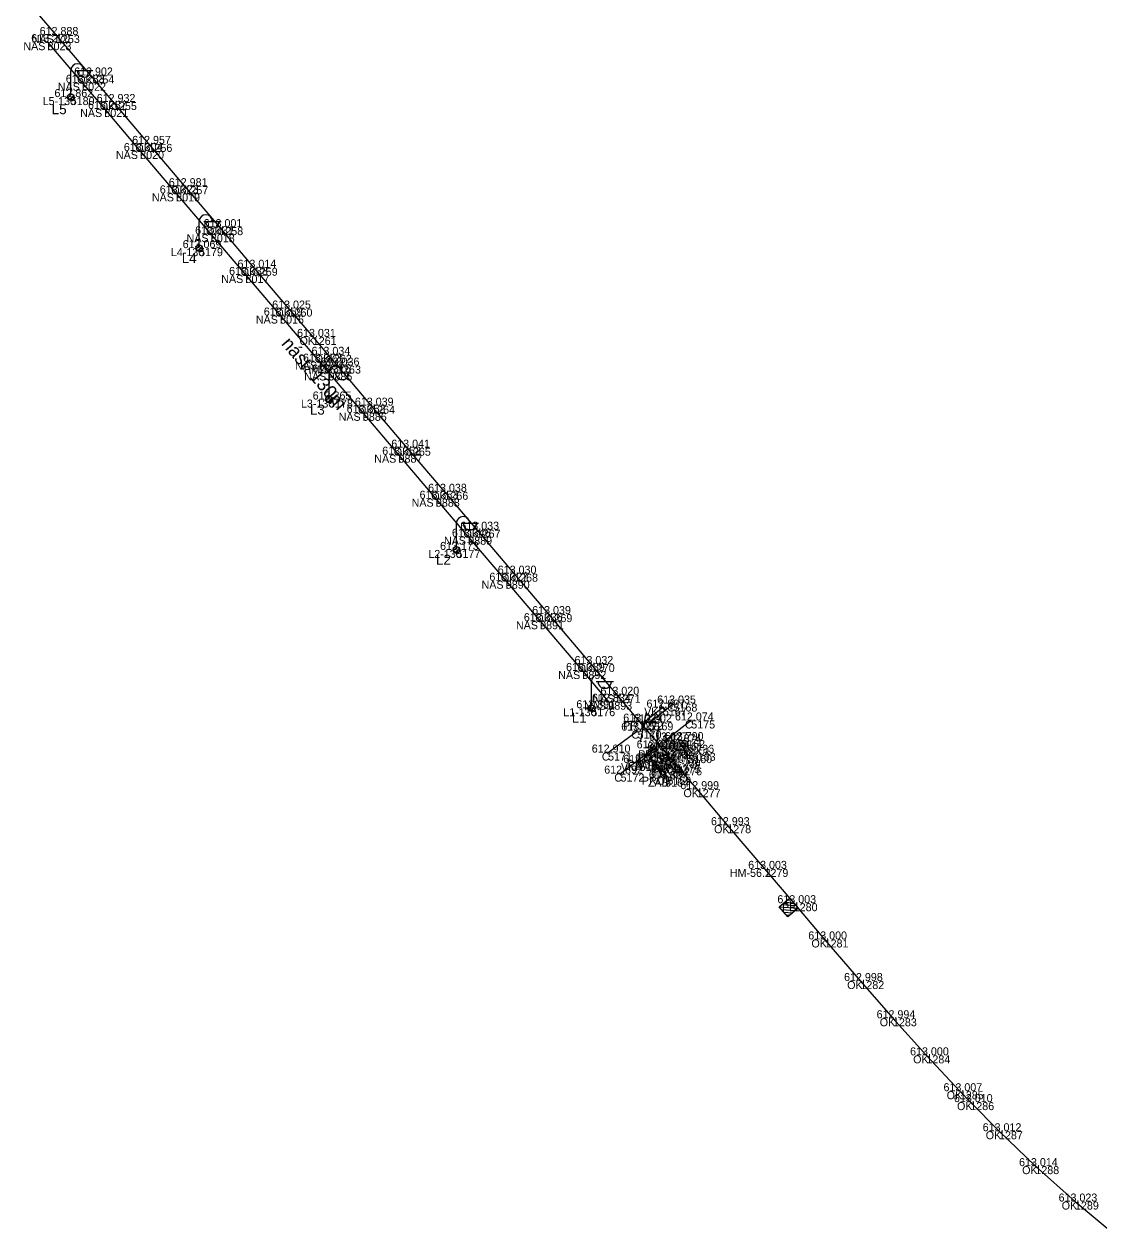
# Model space of a CAD drawing. Extents: x -631472 to -620808, y -1122356 to -1115125.
# Drawn here: x -625291.5 to -625130.5, y -1118428.6 to -1118247.1 of the extents above; entities that cross this region are included whole.
import ezdxf

# ---------------------------------------------------------------- set-up
doc = ezdxf.new("R2010")
doc.units = 0
for name, color, linetype in [('Vrstva 1', 7, 'Continuous'), ('Vrstva 14', 7, 'Continuous'), ('Vrstva 17', 7, 'Continuous'), ('Vrstva 18', 7, 'Continuous'), ('Vrstva 25', 7, 'Continuous'), ('Vrstva 26', 7, 'Continuous'), ('Vrstva 3', 7, 'Continuous'), ('Vrstva 4', 7, 'Continuous'), ('Vrstva 51', 7, 'Continuous'), ('Vrstva 60', 7, 'Continuous'), ('Vrstva 61', 7, 'Continuous'), ('Vrstva 62', 7, 'Continuous')]:
    doc.layers.add(name, color=color, linetype=linetype)

msp = doc.modelspace()

# ---------------------------------------------------------------- linework, layer by layer
at = {"layer": 'Vrstva 1'}
msp.add_lwpolyline([(-625289.52, -1118245.52), (-625286.77, -1118248.75), (-625281.6, -1118254.82), (-625278.22, -1118258.8), (-625272.9, -1118265.08), (-625267.51, -1118271.42), (-625262.28, -1118277.56), (-625257.11, -1118283.65), (-625251.9, -1118289.77), (-625248.28, -1118294.02), (-625246.01, -1118296.7), (-625244.63, -1118298.32), (-625239.52, -1118304.33), (-625234.16, -1118310.63), (-625228.54, -1118317.24), (-625223.7, -1118322.93), (-625218.09, -1118329.52), (-625212.94, -1118335.58), (-625206.59, -1118343.07), (-625202.7, -1118347.67), (-625199.29, -1118351.71), (-625195.67, -1118355.99), (-625195.4, -1118356.31), (-625193.76, -1118358.24), (-625193.5, -1118358.56), (-625190.72, -1118361.83), (-625186.14, -1118367.23), (-625180.56, -1118373.78), (-625176.18, -1118378.93), (-625171.55, -1118384.36), (-625166.19, -1118390.6), (-625161.31, -1118396.18), (-625156.29, -1118401.74), (-625151.28, -1118407.12), (-625149.71, -1118408.75), (-625145.41, -1118413.12), (-625139.96, -1118418.35), (-625134.02, -1118423.66), (-625128.01, -1118428.64)], dxfattribs=at)
at = {"layer": 'Vrstva 14'}
msp.add_lwpolyline([(-625288.03, -1118249.83), (-625282.85, -1118255.92), (-625279.52, -1118259.84), (-625274.15, -1118266.15), (-625268.75, -1118272.5), (-625263.55, -1118278.63), (-625258.36, -1118284.73), (-625253.17, -1118290.82), (-625247.3, -1118297.73), (-625245.92, -1118299.35), (-625240.76, -1118305.4), (-625235.42, -1118311.68), (-625229.82, -1118318.28), (-625224.97, -1118323.98), (-625219.34, -1118330.58), (-625214.19, -1118336.65), (-625207.85, -1118344.11), (-625203.97, -1118348.72)], dxfattribs=at)
at = {"layer": 'Vrstva 17'}
for p, q in [((-625193.05, -1118354.47), (-625191.46, -1118356.37)), ((-625197.49, -1118357.69), (-625195.45, -1118360.24))]:
    msp.add_line(p, q, dxfattribs=at)
at = {"layer": 'Vrstva 18'}
for p, q in [((-625193.37, -1118354.82), (-625191.99, -1118356.72)), ((-625197.26, -1118357.53), (-625195.12, -1118359.96))]:
    msp.add_line(p, q, dxfattribs=at)
at = {"layer": 'Vrstva 25'}
for p, q in [((-625284.56, -1118257.56), (-625284.56, -1118254.06)), ((-625283.86, -1118254.06), (-625281.26, -1118254.06)), ((-625285.03, -1118258.2), (-625284.41, -1118257.58)), ((-625284.8, -1118258.49), (-625284.12, -1118257.82)), ((-625265.32, -1118280.21), (-625265.32, -1118276.71)), ((-625264.62, -1118276.71), (-625262.02, -1118276.71)), ((-625265.8, -1118280.85), (-625265.18, -1118280.23)), ((-625265.56, -1118281.15), (-625264.89, -1118280.47)), ((-625245.84, -1118302.91), (-625245.84, -1118299.41)), ((-625245.14, -1118299.41), (-625242.54, -1118299.41)), ((-625246.31, -1118303.56), (-625245.69, -1118302.94)), ((-625246.08, -1118303.85), (-625245.4, -1118303.17)), ((-625226.74, -1118325.46), (-625226.74, -1118321.96)), ((-625226.04, -1118321.96), (-625223.44, -1118321.96)), ((-625227.22, -1118326.1), (-625226.6, -1118325.48)), ((-625226.98, -1118326.39), (-625226.31, -1118325.72)), ((-625206.52, -1118349.19), (-625206.52, -1118345.69)), ((-625205.82, -1118345.69), (-625203.22, -1118345.69)), ((-625207, -1118349.84), (-625206.38, -1118349.22)), ((-625206.76, -1118350.13), (-625206.08, -1118349.45))]:
    msp.add_line(p, q, dxfattribs=at)
for centre in [(-625284.56, -1118258.06), (-625265.32, -1118280.71), (-625245.84, -1118303.41), (-625226.74, -1118325.96), (-625206.52, -1118349.69)]:
    msp.add_circle(centre, 0.5, dxfattribs=at)
for centre, start, end in [((-625283.56, -1118254.06), 0, 180), ((-625282.56, -1118254.07), 179.2974, 0.7026), ((-625264.32, -1118276.71), 0, 180), ((-625263.32, -1118276.72), 179.2974, 0.7026), ((-625244.84, -1118299.41), 0, 180), ((-625243.84, -1118299.43), 179.2974, 0.7026), ((-625225.74, -1118321.96), 0, 180), ((-625224.74, -1118321.97), 179.2974, 0.7026), ((-625205.52, -1118345.69), 0, 180), ((-625204.52, -1118345.7), 179.2974, 0.7026)]:
    msp.add_arc(centre, 1, start, end, dxfattribs=at)
at = {"layer": 'Vrstva 3'}
for p, q in [((-625178.35, -1118379.47), (-625175.53, -1118379.69)), ((-625178.01, -1118379.87), (-625175.94, -1118380.04)), ((-625177.95, -1118379.12), (-625175.88, -1118379.29)), ((-625177.55, -1118378.78), (-625176.22, -1118378.88)), ((-625177.14, -1118378.43), (-625176.57, -1118378.48)), ((-625177.67, -1118380.27), (-625176.34, -1118380.38)), ((-625177.32, -1118380.68), (-625176.75, -1118380.72))]:
    msp.add_line(p, q, dxfattribs=at)
msp.add_lwpolyline([(-625176.83, -1118378.17), (-625175.53, -1118379.69), (-625177.06, -1118380.99), (-625178.35, -1118379.47)], close=True, dxfattribs=at)
at = {"layer": 'Vrstva 4'}
for p, q in [((-625199.14, -1118354.8), (-625198.26, -1118350.28)), ((-625195.8, -1118349.6), (-625198.54, -1118351.77)), ((-625195.49, -1118349.99), (-625196.11, -1118349.21)), ((-625197.02, -1118351.84), (-625201.63, -1118351.67)), ((-625196.45, -1118352.4), (-625196.9, -1118356.99)), ((-625199.29, -1118357.89), (-625196.76, -1118355.47)), ((-625198.28, -1118355.54), (-625193.68, -1118355.29)), ((-625199.63, -1118357.53), (-625198.94, -1118358.25))]:
    msp.add_line(p, q, dxfattribs=at)
msp.add_lwpolyline([(-625199.29, -1118351.71), (-625195.67, -1118355.99), (-625195.4, -1118356.31)], dxfattribs=at)
at = {"layer": 'Vrstva 51'}
for p, q in [((-625197.8, -1118351.81), (-625194.2, -1118348.99)), ((-625191.54, -1118351.53), (-625195.42, -1118354.53)), ((-625204.01, -1118356.34), (-625199.58, -1118353.06)), ((-625202.14, -1118359.5), (-625197.27, -1118355.71))]:
    msp.add_line(p, q, dxfattribs=at)
at = {"layer": 'Vrstva 60'}
for p, q in [((-625286.77, -1118248.75), (-625286.77, -1118248.75)), ((-625288.03, -1118249.83), (-625288.03, -1118249.83)), ((-625282.85, -1118255.92), (-625282.85, -1118255.92)), ((-625281.6, -1118254.82), (-625281.6, -1118254.82)), ((-625279.52, -1118259.84), (-625279.52, -1118259.84)), ((-625278.22, -1118258.8), (-625278.22, -1118258.8)), ((-625272.9, -1118265.08), (-625272.9, -1118265.08)), ((-625274.15, -1118266.15), (-625274.15, -1118266.15)), ((-625268.75, -1118272.5), (-625268.75, -1118272.5)), ((-625267.51, -1118271.42), (-625267.51, -1118271.42)), ((-625262.28, -1118277.56), (-625262.28, -1118277.56)), ((-625263.55, -1118278.63), (-625263.55, -1118278.63)), ((-625257.11, -1118283.65), (-625257.11, -1118283.65)), ((-625258.36, -1118284.73), (-625258.36, -1118284.73)), ((-625253.17, -1118290.82), (-625253.17, -1118290.82)), ((-625251.9, -1118289.77), (-625251.9, -1118289.77)), ((-625248.28, -1118294.02), (-625248.28, -1118294.02)), ((-625247.3, -1118297.73), (-625247.3, -1118297.73)), ((-625246.01, -1118296.7), (-625246.01, -1118296.7)), ((-625245.92, -1118299.35), (-625245.92, -1118299.35)), ((-625244.63, -1118298.32), (-625244.63, -1118298.32)), ((-625240.76, -1118305.4), (-625240.76, -1118305.4)), ((-625239.52, -1118304.33), (-625239.52, -1118304.33)), ((-625234.16, -1118310.63), (-625234.16, -1118310.63)), ((-625235.42, -1118311.68), (-625235.42, -1118311.68)), ((-625228.54, -1118317.24), (-625228.54, -1118317.24)), ((-625229.82, -1118318.28), (-625229.82, -1118318.28)), ((-625223.7, -1118322.93), (-625223.7, -1118322.93)), ((-625224.97, -1118323.98), (-625224.97, -1118323.98)), ((-625219.34, -1118330.58), (-625219.34, -1118330.58)), ((-625218.09, -1118329.52), (-625218.09, -1118329.52)), ((-625212.94, -1118335.58), (-625212.94, -1118335.58)), ((-625214.19, -1118336.65), (-625214.19, -1118336.65)), ((-625206.59, -1118343.07), (-625206.59, -1118343.07)), ((-625207.85, -1118344.11), (-625207.85, -1118344.11)), ((-625203.97, -1118348.72), (-625203.97, -1118348.72)), ((-625202.7, -1118347.67), (-625202.7, -1118347.67)), ((-625199.29, -1118351.71), (-625199.29, -1118351.71)), ((-625195.67, -1118355.99), (-625195.67, -1118355.99)), ((-625195.4, -1118356.31), (-625195.4, -1118356.31)), ((-625193.76, -1118358.24), (-625193.76, -1118358.24)), ((-625193.5, -1118358.56), (-625193.5, -1118358.56)), ((-625190.72, -1118361.83), (-625190.72, -1118361.83)), ((-625186.14, -1118367.23), (-625186.14, -1118367.23)), ((-625180.56, -1118373.78), (-625180.56, -1118373.78)), ((-625176.18, -1118378.93), (-625176.18, -1118378.93)), ((-625171.55, -1118384.36), (-625171.55, -1118384.36)), ((-625166.19, -1118390.6), (-625166.19, -1118390.6)), ((-625161.31, -1118396.18), (-625161.31, -1118396.18)), ((-625156.29, -1118401.74), (-625156.29, -1118401.74)), ((-625151.28, -1118407.12), (-625151.28, -1118407.12)), ((-625149.71, -1118408.75), (-625149.71, -1118408.75)), ((-625145.41, -1118413.12), (-625145.41, -1118413.12)), ((-625139.96, -1118418.35), (-625139.96, -1118418.35)), ((-625134.02, -1118423.66), (-625134.02, -1118423.66))]:
    msp.add_line(p, q, dxfattribs=at)

# ---------------------------------------------------------------- texts
at = {"layer": 'Vrstva 14'}
msp.add_text('nást. 130m', height=2, rotation=310.3614, dxfattribs=at).set_placement((-625253.08, -1118295.09))
at = {"layer": 'Vrstva 26'}
for s, p in [('L5', (-625287.41, -1118260.63)), ('L4', (-625267.92, -1118282.96)), ('L3', (-625248.71, -1118305.67)), ('L2', (-625229.8, -1118328.16)), ('L1', (-625209.45, -1118351.85))]:
    msp.add_text(s, height=1.5, dxfattribs=at).set_placement(p)
at = {"layer": 'Vrstva 60'}
for s, p in [('1253', (-625286.77, -1118249.95)), ('8023', (-625288.03, -1118251.03)), ('8022', (-625282.85, -1118257.12)), ('1254', (-625281.6, -1118256.02)), ('5180', (-625284.56, -1118259.26)), ('8021', (-625279.52, -1118261.04)), ('1255', (-625278.22, -1118260)), ('1256', (-625272.9, -1118266.28)), ('8020', (-625274.15, -1118267.34)), ('8019', (-625268.75, -1118273.7)), ('1257', (-625267.51, -1118272.62)), ('1258', (-625262.28, -1118278.76)), ('8018', (-625263.55, -1118279.83)), ('5179', (-625265.32, -1118281.91)), ('1259', (-625257.11, -1118284.85)), ('8017', (-625258.36, -1118285.93)), ('8016', (-625253.17, -1118292.02)), ('1260', (-625251.9, -1118290.97)), ('1261', (-625248.28, -1118295.22)), ('9884', (-625247.3, -1118298.93)), ('1262', (-625246.01, -1118297.9)), ('9885', (-625245.92, -1118300.55)), ('1263', (-625244.63, -1118299.52)), ('5178', (-625245.84, -1118304.61)), ('9886', (-625240.76, -1118306.6)), ('1264', (-625239.52, -1118305.53)), ('1265', (-625234.16, -1118311.83)), ('9887', (-625235.42, -1118312.88)), ('1266', (-625228.54, -1118318.44)), ('9888', (-625229.82, -1118319.48)), ('1267', (-625223.7, -1118324.12)), ('9889', (-625224.97, -1118325.18)), ('5177', (-625226.74, -1118327.16)), ('9890', (-625219.34, -1118331.78)), ('1268', (-625218.09, -1118330.72)), ('1269', (-625212.94, -1118336.78)), ('9891', (-625214.19, -1118337.85)), ('1270', (-625206.59, -1118344.27)), ('9892', (-625207.85, -1118345.31)), ('9893', (-625203.97, -1118349.92)), ('1271', (-625202.7, -1118348.87)), ('5168', (-625194.2, -1118350.19)), ('5176', (-625206.52, -1118350.89)), ('5167', (-625195.8, -1118350.8)), ('1272', (-625199.29, -1118352.91)), ('5169', (-625197.8, -1118353.01)), ('5175', (-625191.54, -1118352.73)), ('5170', (-625199.58, -1118354.26)), ('5174', (-625195.42, -1118355.74)), ('5162', (-625193.05, -1118355.67)), ('5171', (-625204.01, -1118357.54)), ('5173', (-625197.27, -1118356.91)), ('1273', (-625195.67, -1118357.19)), ('1274', (-625195.4, -1118357.51)), ('5161', (-625193.37, -1118356.02)), ('5163', (-625191.46, -1118357.57)), ('5166', (-625199.29, -1118359.09)), ('5165', (-625197.49, -1118358.89)), ('5158', (-625197.26, -1118358.73)), ('5160', (-625191.99, -1118357.92)), ('5172', (-625202.14, -1118360.7)), ('5159', (-625195.12, -1118361.16)), ('1275', (-625193.76, -1118359.44)), ('1276', (-625193.5, -1118359.76)), ('5164', (-625195.45, -1118361.44)), ('1277', (-625190.72, -1118363.03)), ('1278', (-625186.14, -1118368.43)), ('1279', (-625180.56, -1118374.98)), ('1280', (-625176.18, -1118380.13)), ('1281', (-625171.55, -1118385.56)), ('1282', (-625166.19, -1118391.8)), ('1283', (-625161.31, -1118397.38)), ('1284', (-625156.29, -1118402.94)), ('1285', (-625151.28, -1118408.32)), ('1286', (-625149.71, -1118409.95)), ('1287', (-625145.41, -1118414.32)), ('1288', (-625139.96, -1118419.55)), ('1289', (-625134.02, -1118424.86))]:
    msp.add_text(s, height=1.2, dxfattribs=at).set_placement(p)
at = {"layer": 'Vrstva 61'}
for s, p in [('613.270', (-625290.48, -1118249.83)), ('612.888', (-625289.22, -1118248.75)), ('613.283', (-625285.3, -1118255.92)), ('612.902', (-625284.05, -1118254.82)), ('612.862', (-625287, -1118258.06)), ('612.932', (-625280.67, -1118258.8)), ('613.287', (-625281.97, -1118259.84)), ('613.304', (-625276.6, -1118266.15)), ('612.957', (-625275.35, -1118265.08)), ('612.981', (-625269.86, -1118271.42)), ('613.323', (-625271.21, -1118272.5)), ('613.001', (-625264.64, -1118277.56)), ('613.331', (-625265.91, -1118278.63)), ('613.069', (-625267.78, -1118280.71)), ('613.338', (-625260.82, -1118284.73)), ('613.014', (-625259.56, -1118283.65)), ('613.025', (-625254.36, -1118289.77)), ('613.359', (-625255.62, -1118290.82)), ('613.031', (-625250.63, -1118294.02)), ('613.034', (-625248.46, -1118296.7)), ('613.373', (-625249.75, -1118297.73)), ('613.376', (-625248.37, -1118299.35)), ('613.036', (-625247.08, -1118298.32)), ('613.265', (-625248.29, -1118303.41)), ('613.039', (-625241.97, -1118304.33)), ('613.352', (-625243.2, -1118305.4)), ('613.352', (-625237.87, -1118311.68)), ('613.041', (-625236.51, -1118310.63)), ('613.038', (-625230.99, -1118317.24)), ('613.353', (-625232.27, -1118318.28)), ('613.033', (-625226.15, -1118322.93)), ('613.346', (-625227.42, -1118323.98)), ('613.173', (-625229.2, -1118325.96)), ('613.030', (-625220.55, -1118329.52)), ('613.327', (-625221.8, -1118330.58)), ('613.039', (-625215.39, -1118335.58)), ('613.336', (-625216.64, -1118336.65)), ('613.339', (-625210.31, -1118344.11)), ('613.032', (-625209.04, -1118343.07)), ('613.020', (-625205.15, -1118347.67)), ('612.891', (-625208.77, -1118349.69)), ('612.834', (-625206.42, -1118348.72)), ('612.897', (-625198.25, -1118349.6)), ('613.035', (-625196.65, -1118348.99)), ('613.024', (-625201.74, -1118351.71)), ('613.002', (-625200.25, -1118351.81)), ('612.074', (-625193.99, -1118351.53)), ('613.005', (-625202.04, -1118353.06)), ('613.015', (-625199.73, -1118355.71)), ('613.027', (-625197.87, -1118354.53)), ('612.874', (-625195.82, -1118354.82)), ('613.790', (-625195.5, -1118354.47)), ('612.910', (-625206.46, -1118356.34)), ('612.871', (-625199.52, -1118357.53)), ('613.015', (-625198.13, -1118355.99)), ('613.014', (-625197.85, -1118356.31)), ('612.902', (-625194.44, -1118356.72)), ('613.796', (-625193.91, -1118356.37)), ('613.005', (-625201.74, -1118357.89)), ('613.883', (-625199.94, -1118357.69)), ('613.001', (-625196.12, -1118358.24)), ('613.000', (-625195.95, -1118358.56)), ('612.892', (-625204.59, -1118359.5)), ('613.827', (-625197.9, -1118360.24)), ('612.807', (-625197.57, -1118359.96)), ('612.999', (-625193.18, -1118361.83)), ('612.993', (-625188.59, -1118367.23)), ('613.003', (-625183.01, -1118373.78)), ('613.003', (-625178.63, -1118378.93)), ('613.000', (-625174, -1118384.36)), ('612.998', (-625168.64, -1118390.6)), ('612.994', (-625163.76, -1118396.18)), ('613.000', (-625158.74, -1118401.74)), ('613.007', (-625153.73, -1118407.12)), ('613.010', (-625152.17, -1118408.75)), ('613.012', (-625147.86, -1118413.12)), ('613.014', (-625142.41, -1118418.35)), ('613.023', (-625136.48, -1118423.66))]:
    msp.add_text(s, height=1.2, dxfattribs=at).set_placement(p)
at = {"layer": 'Vrstva 62'}
for s, p in [('NAST', (-625290.41, -1118249.95)), ('NAST', (-625291.66, -1118251.03)), ('NAST', (-625286.49, -1118257.12)), ('OK', (-625283.59, -1118256.02)), ('L5-130', (-625288.77, -1118259.26)), ('NAST', (-625283.15, -1118261.04)), ('OK', (-625280.21, -1118260)), ('OK', (-625274.88, -1118266.28)), ('NAST', (-625277.79, -1118267.34)), ('NAST', (-625272.39, -1118273.7)), ('OK', (-625269.49, -1118272.62)), ('OK', (-625264.27, -1118278.76)), ('NAST', (-625267.19, -1118279.83)), ('L4-130', (-625269.54, -1118281.91)), ('OK', (-625259.09, -1118284.85)), ('NAST', (-625262, -1118285.93)), ('NAST', (-625256.81, -1118292.02)), ('OK', (-625253.89, -1118290.97)), ('OK', (-625250.26, -1118295.22)), ('NAST', (-625250.94, -1118298.93)), ('OK', (-625247.99, -1118297.9)), ('HM-56.1', (-625249.65, -1118299.52)), ('NAST', (-625249.56, -1118300.55)), ('L3-130', (-625250.05, -1118304.61)), ('NAST', (-625244.4, -1118306.6)), ('OK', (-625241.5, -1118305.53)), ('OK', (-625236.14, -1118311.83)), ('NAST', (-625239.06, -1118312.88)), ('OK', (-625230.52, -1118318.44)), ('NAST', (-625233.46, -1118319.48)), ('OK', (-625225.69, -1118324.12)), ('NAST', (-625228.61, -1118325.18)), ('L2-130', (-625230.96, -1118327.16)), ('NAST', (-625222.98, -1118331.78)), ('OK', (-625220.08, -1118330.72)), ('OK', (-625214.92, -1118336.78)), ('NAST', (-625217.82, -1118337.85)), ('OK', (-625208.58, -1118344.27)), ('NAST', (-625211.49, -1118345.31)), ('NAST', (-625207.61, -1118349.92)), ('NAST', (-625206.34, -1118348.87)), ('C', (-625195.13, -1118350.19)), ('L1-130', (-625210.73, -1118350.89)), ('VKR', (-625198.61, -1118350.8)), ('PRJ', (-625201.77, -1118352.91)), ('C', (-625198.74, -1118353.01)), ('C', (-625192.48, -1118352.73)), ('C', (-625200.51, -1118354.26)), ('C', (-625196.36, -1118355.74)), ('ZAB', (-625195.65, -1118355.67)), ('C', (-625204.95, -1118357.54)), ('PROP', (-625199.51, -1118357.19)), ('C', (-625198.2, -1118356.91)), ('PRJ', (-625197.89, -1118357.51)), ('PROP', (-625197.21, -1118356.02)), ('VKR', (-625202.09, -1118359.09)), ('PROP', (-625201.1, -1118358.73)), ('ZAB', (-625200.09, -1118358.89)), ('PROP', (-625195.83, -1118357.92)), ('ZAB', (-625194.06, -1118357.57)), ('C', (-625203.08, -1118360.7)), ('PROP', (-625198.95, -1118361.16)), ('PROP', (-625197.6, -1118359.44)), ('PROP', (-625197.33, -1118359.76)), ('ZAB', (-625198.05, -1118361.44)), ('OK', (-625192.71, -1118363.03)), ('OK', (-625188.12, -1118368.43)), ('HM-56.2', (-625185.76, -1118374.98)), ('PB', (-625177.94, -1118380.13)), ('OK', (-625173.53, -1118385.56)), ('OK', (-625168.17, -1118391.8)), ('OK', (-625163.29, -1118397.38)), ('OK', (-625158.28, -1118402.94)), ('OK', (-625153.26, -1118408.32)), ('OK', (-625151.7, -1118409.95)), ('OK', (-625147.4, -1118414.32)), ('OK', (-625141.94, -1118419.55)), ('OK', (-625136.01, -1118424.86))]:
    msp.add_text(s, height=1.2, dxfattribs=at).set_placement(p)

doc.saveas('drawing.dxf')
